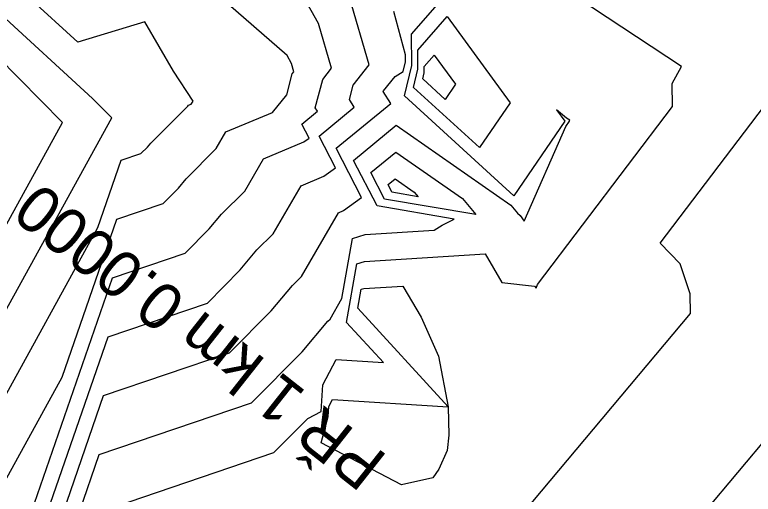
# Model space of a CAD drawing. Extents: x -549394 to -546608, y -1037055 to -1033629.
# Drawn here: x -547550.6 to -547406.7, y -1035525.2 to -1035431.6 of the extents above; entities that cross this region are included whole.
import ezdxf

# ---------------------------------------------------------------- set-up
doc = ezdxf.new("R2010")
doc.units = 0
for name, color, linetype in [('hlavni_vrst', 7, 'Continuous'), ('norm_vrst', 7, 'Continuous'), ('x_popis_pricne_rezy_C11', 7, 'Continuous')]:
    doc.layers.add(name, color=color, linetype=linetype)

msp = doc.modelspace()

# ---------------------------------------------------------------- linework, layer by layer
at = {"layer": 'hlavni_vrst'}
for p, q in [((-547535.45, -1035447.95), (-547554.28, -1035430.67)), ((-547474.46, -1035439.45), (-547476.7, -1035430.96)), ((-547474.46, -1035440.83), (-547474.46, -1035439.45)), ((-547474.92, -1035442.69), (-547474.46, -1035440.83)), ((-547476.48, -1035443.66), (-547474.92, -1035442.69)), ((-547478.74, -1035446.47), (-547476.48, -1035443.66)), ((-547478.77, -1035446.61), (-547478.74, -1035446.47)), ((-547477.32, -1035448.91), (-547478.77, -1035446.61)), ((-547531.7, -1035451.74), (-547535.45, -1035447.95)), ((-547487.93, -1035457.67), (-547477.32, -1035448.91)), ((-547574.09, -1035528.75), (-547531.7, -1035451.74)), ((-547483, -1035467.27), (-547487.93, -1035457.67)), ((-547486.51, -1035469.83), (-547483, -1035467.27)), ((-547494.7, -1035482.67), (-547487.48, -1035470.23)), ((-547487.48, -1035470.23), (-547486.51, -1035469.83)), ((-547496.48, -1035484.45), (-547494.7, -1035482.67)), ((-547500.62, -1035489.39), (-547496.48, -1035484.45)), ((-547508.74, -1035497.6), (-547500.62, -1035489.39)), ((-547533.27, -1035505.92), (-547508.74, -1035497.6)), ((-547550.08, -1035554.5), (-547533.27, -1035505.92))]:
    msp.add_line(p, q, dxfattribs=at)
at = {"layer": 'norm_vrst'}
for p, q in [((-547497.54, -1035439.58), (-547515.07, -1035424.23)), ((-547491.42, -1035433.34), (-547496.28, -1035424.65)), ((-547481.5, -1035441.41), (-547486.17, -1035425.52)), ((-547538.3, -1035436.99), (-547550.32, -1035425.96)), ((-547473.26, -1035435.41), (-547467.3, -1035428.51)), ((-547420.65, -1035441.72), (-547442.43, -1035427.31)), ((-547472.03, -1035438.56), (-547466.35, -1035431.99)), ((-547466.35, -1035431.99), (-547454.06, -1035448.78)), ((-547525.22, -1035433.03), (-547538.3, -1035436.99)), ((-547519.65, -1035442.63), (-547525.22, -1035433.03)), ((-547488.85, -1035442.07), (-547491.42, -1035433.34)), ((-547541.28, -1035452.65), (-547558.45, -1035435.28)), ((-547473.24, -1035441.54), (-547473.26, -1035435.41)), ((-547472.02, -1035442.25), (-547472.03, -1035438.56)), ((-547496.67, -1035441.15), (-547497.54, -1035439.58)), ((-547470.8, -1035441.71), (-547468.88, -1035439.49)), ((-547468.88, -1035439.49), (-547464.73, -1035445.16)), ((-547496.2, -1035442.73), (-547496.67, -1035441.15)), ((-547484.66, -1035445.35), (-547481.5, -1035441.41)), ((-547474.67, -1035447.42), (-547473.24, -1035441.54)), ((-547515.81, -1035448.5), (-547519.65, -1035442.63)), ((-547496.52, -1035443.12), (-547496.2, -1035442.73)), ((-547490.59, -1035444.24), (-547488.85, -1035442.07)), ((-547472.88, -1035445.79), (-547472.02, -1035442.25)), ((-547471.08, -1035444.15), (-547470.79, -1035442.96)), ((-547470.79, -1035442.96), (-547470.8, -1035441.71)), ((-547422.49, -1035445.05), (-547420.65, -1035441.72)), ((-547497.58, -1035447.24), (-547496.52, -1035443.12)), ((-547492.02, -1035449.75), (-547490.59, -1035444.24)), ((-547466.74, -1035448.12), (-547471.08, -1035444.15)), ((-547485.39, -1035448.18), (-547484.66, -1035445.35)), ((-547460.03, -1035457.54), (-547472.88, -1035445.79)), ((-547464.73, -1035445.16), (-547466.74, -1035448.12)), ((-547422.44, -1035449.51), (-547422.49, -1035445.05)), ((-547500.39, -1035450.7), (-547497.58, -1035447.24)), ((-547424.79, -1035476.2), (-547402.4, -1035446.61)), ((-547516.24, -1035449.03), (-547515.81, -1035448.5)), ((-547484.46, -1035449.66), (-547485.39, -1035448.18)), ((-547453.31, -1035466.95), (-547474.67, -1035447.42)), ((-547524.1, -1035456.65), (-547516.86, -1035449.43)), ((-547516.86, -1035449.43), (-547516.75, -1035449.24)), ((-547516.75, -1035449.24), (-547516.24, -1035449.03)), ((-547491.6, -1035450.41), (-547492.02, -1035449.75)), ((-547491.29, -1035455.3), (-547484.46, -1035449.66)), ((-547454.06, -1035448.78), (-547460.03, -1035457.54)), ((-547448.7, -1035484.23), (-547422.44, -1035449.51)), ((-547443.05, -1035451.77), (-547445.03, -1035450.16)), ((-547445.03, -1035450.16), (-547443.39, -1035452.39)), ((-547509.43, -1035454.49), (-547500.39, -1035450.7)), ((-547494.66, -1035452.94), (-547491.6, -1035450.41)), ((-547579.26, -1035521.64), (-547541.28, -1035452.65)), ((-547493.23, -1035455.7), (-547494.66, -1035452.94)), ((-547443.39, -1035452.39), (-547453.31, -1035466.95)), ((-547443.23, -1035453.42), (-547442.47, -1035452.41)), ((-547442.42, -1035452.19), (-547443.05, -1035451.77)), ((-547442.47, -1035452.28), (-547442.42, -1035452.19)), ((-547442.47, -1035452.41), (-547442.47, -1035452.28)), ((-547511.32, -1035457.74), (-547509.43, -1035454.49)), ((-547484.57, -1035460.03), (-547476.26, -1035453.18)), ((-547476.26, -1035453.18), (-547453.9, -1035468.74)), ((-547451.32, -1035471.89), (-547443.23, -1035453.42)), ((-547494.25, -1035456.44), (-547493.23, -1035455.7)), ((-547488.12, -1035461.49), (-547491.29, -1035455.3)), ((-547524.75, -1035457.42), (-547524.1, -1035456.65)), ((-547502.11, -1035459.74), (-547494.25, -1035456.44)), ((-547529.84, -1035460), (-547526.02, -1035458.71)), ((-547526.02, -1035458.71), (-547524.75, -1035457.42)), ((-547517.2, -1035463.6), (-547511.32, -1035457.74)), ((-547481.21, -1035462.4), (-547476.36, -1035458.4)), ((-547476.36, -1035458.4), (-547463.32, -1035467.48)), ((-547534.38, -1035473.12), (-547529.84, -1035460)), ((-547505.78, -1035466.05), (-547502.11, -1035459.74)), ((-547480, -1035468.92), (-547484.57, -1035460.03)), ((-547490.38, -1035463.13), (-547488.12, -1035461.49)), ((-547494.8, -1035464.98), (-547490.38, -1035463.13)), ((-547478.54, -1035467.58), (-547481.21, -1035462.4)), ((-547518.71, -1035465.42), (-547517.2, -1035463.6)), ((-547477.84, -1035464.76), (-547476.46, -1035463.62)), ((-547476.46, -1035463.62), (-547472.73, -1035466.22)), ((-547521.7, -1035468.43), (-547518.71, -1035465.42)), ((-547500.24, -1035474.36), (-547494.8, -1035464.98)), ((-547477.08, -1035466.25), (-547477.84, -1035464.76)), ((-547510.29, -1035470.55), (-547505.78, -1035466.05)), ((-547472, -1035467.11), (-547477.08, -1035466.25)), ((-547472.73, -1035466.22), (-547472, -1035467.11)), ((-547463.32, -1035467.48), (-547460.76, -1035470.6)), ((-547530.7, -1035471.48), (-547521.7, -1035468.43)), ((-547460.76, -1035470.6), (-547478.54, -1035467.58)), ((-547453.9, -1035468.74), (-547452.6, -1035470.32)), ((-547464.97, -1035471.47), (-547480, -1035468.92)), ((-547452.6, -1035470.32), (-547452.1, -1035470.81)), ((-547541.37, -1035502.32), (-547530.7, -1035471.48)), ((-547512.68, -1035473.41), (-547510.29, -1035470.55)), ((-547467.33, -1035472.68), (-547464.97, -1035471.47)), ((-547452.1, -1035470.81), (-547451.32, -1035471.89)), ((-547568.92, -1035535.86), (-547534.38, -1035473.12)), ((-547468.86, -1035473.62), (-547467.33, -1035472.68)), ((-547517.38, -1035478.15), (-547512.68, -1035473.41)), ((-547503.39, -1035477.5), (-547500.24, -1035474.36)), ((-547484.8, -1035475.27), (-547482.34, -1035474.48)), ((-547482.34, -1035474.48), (-547468.86, -1035473.62)), ((-547486.84, -1035486.97), (-547484.8, -1035475.27)), ((-547506.65, -1035481.4), (-547503.39, -1035477.5)), ((-547420.91, -1035480.2), (-547424.79, -1035476.2)), ((-547531.56, -1035482.96), (-547517.38, -1035478.15)), ((-547482.46, -1035479.76), (-547458.95, -1035478.26)), ((-547458.95, -1035478.26), (-547455.65, -1035483.86)), ((-547485.92, -1035491.65), (-547483.94, -1035480.22)), ((-547483.94, -1035480.22), (-547482.46, -1035479.76)), ((-547418.94, -1035486.04), (-547420.91, -1035480.2)), ((-547513.06, -1035487.87), (-547506.65, -1035481.4)), ((-547548.36, -1035531.52), (-547531.56, -1035482.96)), ((-547482.59, -1035485.03), (-547474.96, -1035484.54)), ((-547474.96, -1035484.54), (-547471.37, -1035490.63)), ((-547455.65, -1035483.86), (-547449.3, -1035484.55)), ((-547449.3, -1035484.55), (-547449.01, -1035484.94)), ((-547449.01, -1035484.94), (-547448.7, -1035484.23)), ((-547483.71, -1035488.88), (-547483.07, -1035485.18)), ((-547483.07, -1035485.18), (-547482.59, -1035485.03)), ((-547418.88, -1035489.89), (-547418.94, -1035486.04)), ((-547489.16, -1035490.97), (-547486.84, -1035486.97)), ((-547532.42, -1035494.44), (-547513.06, -1035487.87)), ((-547466.16, -1035508.08), (-547483.71, -1035488.88)), ((-547464.74, -1035544.58), (-547418.88, -1035489.89)), ((-547494.59, -1035497.38), (-547489.58, -1035491.4)), ((-547489.58, -1035491.4), (-547489.16, -1035490.97)), ((-547478.75, -1035499.48), (-547485.92, -1035491.65)), ((-547471.37, -1035490.63), (-547468.03, -1035498.2)), ((-547553.66, -1035555.84), (-547532.42, -1035494.44)), ((-547424.07, -1035538.01), (-547387.59, -1035494.51)), ((-547504.43, -1035507.32), (-547494.59, -1035497.38)), ((-547490.59, -1035503.8), (-547487.94, -1035498.9)), ((-547487.94, -1035498.9), (-547478.75, -1035499.48)), ((-547468.03, -1035498.2), (-547466.16, -1035508.08)), ((-547563.74, -1035542.97), (-547541.37, -1035502.32)), ((-547490.91, -1035509), (-547490.59, -1035503.8)), ((-547534.13, -1035517.4), (-547504.43, -1035507.32)), ((-547489.41, -1035508.05), (-547488.65, -1035506.65)), ((-547488.65, -1035506.65), (-547466.16, -1035508.08)), ((-547493.49, -1035510.36), (-547490.91, -1035509)), ((-547489.53, -1035509.98), (-547489.41, -1035508.05)), ((-547466.16, -1035508.08), (-547466.16, -1035508.08)), ((-547466.16, -1035508.08), (-547466.02, -1035513.62)), ((-547466.16, -1035508.08), (-547466.16, -1035508.08)), ((-547500.11, -1035517.04), (-547493.49, -1035510.36)), ((-547490.86, -1035515.15), (-547489.53, -1035509.98)), ((-547466.02, -1035513.62), (-547466.34, -1035516.65)), ((-547475.23, -1035523.29), (-547490.86, -1035515.15)), ((-547546.5, -1035553.16), (-547534.13, -1035517.4)), ((-547534.99, -1035528.88), (-547500.11, -1035517.04)), ((-547466.34, -1035516.65), (-547467.95, -1035520.28)), ((-547467.95, -1035520.28), (-547469.11, -1035521.93)), ((-547469.11, -1035521.93), (-547475.23, -1035523.29))]:
    msp.add_line(p, q, dxfattribs=at)

# ---------------------------------------------------------------- texts
at = {"layer": 'x_popis_pricne_rezy_C11'}
msp.add_text('PŘ 1 km 0.0000', height=9.0627, rotation=141.71, dxfattribs=at).set_placement((-547477.65, -1035517.85))

doc.saveas('drawing.dxf')
